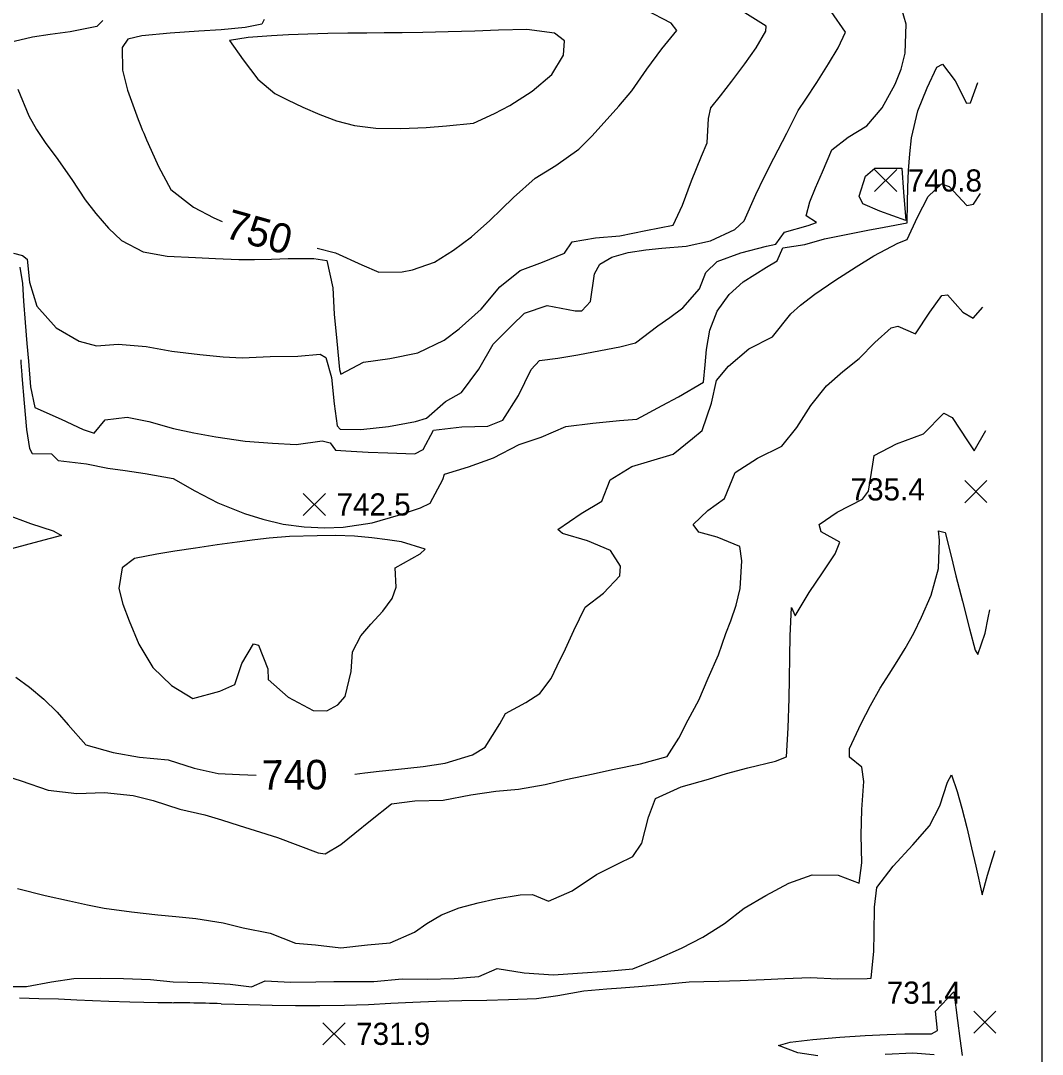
# Model space of a CAD drawing. Extents: x 2566079 to 2571326, y 424054 to 426896.
# Drawn here: x 2570611 to 2571303, y 425217 to 425917 of the extents above; entities that cross this region are included whole.
import ezdxf

# ---------------------------------------------------------------- set-up
doc = ezdxf.new("R2010")
doc.units = 0
for name, color, linetype in [('Contour_ADS_Label_Major', 7, 'Continuous'), ('Contour_ADS_Major', 7, 'Continuous'), ('Contour_ADS_Minor', 7, 'Continuous'), ('Contour_ADS_Spot_Elevation', 7, 'Continuous'), ('Contour_ADS_State_Plane_Border', 7, 'Continuous')]:
    doc.layers.add(name, color=color, linetype=linetype)

# ---------------------------------------------------------------- blocks, each defined once
blk = doc.blocks.new('S750')
at = {"layer": 'Contour_ADS_Spot_Elevation'}
for p, q in [((-0.5, 0.498), (0.5, -0.498)), ((-0.498, -0.5), (0.498, 0.5))]:
    blk.add_line(p, q, dxfattribs=at)

msp = doc.modelspace()

# ---------------------------------------------------------------- linework, layer by layer
at = {"layer": 'Contour_ADS_Major'}
for points in [[(2570811.84, 425762.74), (2570824.23, 425759.65), (2570842.23, 425751.41), (2570853.78, 425746.59), (2570869.41, 425746.79), (2570876.51, 425747.97), (2570891.26, 425753.24), (2570904.12, 425761.33), (2570916.5, 425770.5), (2570928.73, 425781.47), (2570936.67, 425789.06), (2570944.91, 425796.97), (2570959.43, 425810.1), (2570973.47, 425818.75), (2570989.15, 425829.87), (2570997.79, 425838.59), (2571006.2, 425847.78), (2571016.23, 425858.93), (2571025.08, 425869.19), (2571035.12, 425883.89), (2571045.19, 425897.82), (2571055.34, 425910.19), (2571051.6, 425915.17), (2571034.16, 425924.26)], [(2570776.12, 425917.51), (2570774.38, 425914.39), (2570763.17, 425912.13), (2570746.88, 425910.67), (2570731.75, 425909.75), (2570712.3, 425908.36), (2570693.3, 425906.6), (2570683.61, 425904.24), (2570679.87, 425898.73), (2570680.12, 425883.28), (2570683.52, 425869.84), (2570689.77, 425852.29)], [(2570697.41, 425833.73), (2570704.5, 425817.99), (2570712.8, 425802.58), (2570728.29, 425790.49), (2570741.94, 425783.26), (2570747.65, 425780.76)], [(2570837.35, 425406.4), (2570844.23, 425407.36), (2570854, 425408.53), (2570864.86, 425409.75), (2570883.65, 425411.67), (2570898.59, 425413.95), (2570917.07, 425419.53), (2570925.65, 425424.7), (2570935.55, 425440.67), (2570939.55, 425447.7), (2570953.14, 425455.05), (2570962.79, 425461.17), (2570970.26, 425471.28), (2570974.53, 425479.86), (2570980.03, 425491.47), (2570985.8, 425503.8), (2570993.46, 425519.6), (2571005.71, 425529.1), (2571016.8, 425540.86), (2571017.21, 425547.33), (2571010.58, 425557.96), (2570994.96, 425564.57), (2570977.94, 425569.52), (2570974.87, 425572.29), (2570990.63, 425583.09), (2571004.7, 425591.35), (2571010.34, 425605.88), (2571025.07, 425614.86), (2571035.51, 425618.11), (2571052.87, 425623.29), (2571066, 425633.77), (2571072.54, 425639.22), (2571078.86, 425657.88), (2571082.22, 425673.07), (2571090.38, 425682.94), (2571104.18, 425694.63), (2571120.16, 425702.63), (2571132.63, 425718.21), (2571139.15, 425724.15), (2571149, 425731.63), (2571162.46, 425740.74), (2571176.88, 425750.01), (2571188.88, 425757.54), (2571205.11, 425766.07), (2571211.41, 425768.57), (2571218.51, 425783.83), (2571225.64, 425797.83), (2571234.66, 425806.32), (2571239.91, 425804.58), (2571251.82, 425791.67), (2571256.29, 425792.61), (2571261.04, 425799.83)], [(2570600.98, 425582.5), (2570617.88, 425576.37), (2570633.21, 425571.34), (2570638.8, 425568.14), (2570623.46, 425563.99), (2570604.85, 425559.08)], [(2570607.87, 425472.23), (2570617.18, 425465.34), (2570626.89, 425457.24), (2570635.76, 425448.44), (2570643.23, 425440.03), (2570655.17, 425426.4), (2570673.69, 425421.07), (2570691.69, 425417.99), (2570711.08, 425416.3), (2570728.7, 425410.68), (2570744.85, 425407.01), (2570759.31, 425406.3), (2570770.68, 425405.87)], [(2571150.86, 425215.85), (2571137.48, 425217.8), (2571124.3, 425222.68), (2571132.12, 425224.95), (2571147.46, 425226.89), (2571165.72, 425228.44), (2571182.94, 425229.54), (2571197.84, 425230.24), (2571209.82, 425230.61), (2571227.98, 425230.56), (2571231.99, 425232.84), (2571231.99, 425232.84), (2571230.63, 425245.97), (2571242.93, 425259.06), (2571245.57, 425239.74), (2571247.16, 425227.51), (2571248.61, 425215.93)], [(2571229.74, 425216.37), (2571215.17, 425217.57), (2571196.61, 425216.58)]]:
    msp.add_lwpolyline(points, dxfattribs=at)
msp.add_arc((2571144.99, 426028.82), 488.25, 201.19619, 203.55166, dxfattribs=at)
at = {"layer": 'Contour_ADS_Minor'}
for points in [[(2570610.66, 425749.85), (2570612.3, 425738.73), (2570613.13, 425726.84), (2570614.25, 425712.41), (2570615.4, 425698.13), (2570616.35, 425686.14), (2570617.8, 425668.82), (2570620.73, 425654.88), (2570638.65, 425646.92), (2570653.47, 425639.87), (2570660.9, 425637.45), (2570668.35, 425646.59), (2570683.16, 425648.33), (2570697.9, 425645.31), (2570714.63, 425640.52), (2570728.49, 425637.58), (2570743.38, 425634.94), (2570763.08, 425632.07), (2570781.61, 425630.61), (2570797.72, 425629.7), (2570815.28, 425632.34), (2570820.75, 425630.95), (2570824.31, 425625.98), (2570834.95, 425625.22), (2570846.46, 425624.69), (2570859.69, 425624.05), (2570878.14, 425623.52), (2570883.6, 425626.32), (2570890.7, 425639.53), (2570909.78, 425641.69), (2570927.4, 425642.18), (2570937.72, 425646.29), (2570948.25, 425662.93), (2570956.86, 425680.48), (2570962.43, 425686.61), (2570974.84, 425688.19), (2570988.34, 425690.41), (2571003.84, 425693.34), (2571016.91, 425695.94), (2571027.51, 425698.53), (2571042.5, 425710.17), (2571050.8, 425715.87), (2571059.51, 425722.28), (2571070.9, 425735.29), (2571075.1, 425746.23), (2571082.71, 425753.73), (2571098.71, 425759.62), (2571116.08, 425764.02), (2571122.48, 425765.55), (2571128.45, 425773.59), (2571144.47, 425778.1), (2571150.1, 425780.15), (2571143.06, 425784.55), (2571145.5, 425794.18), (2571149.4, 425803.57), (2571154.01, 425814.51), (2571160.46, 425829.43), (2571171.4, 425837.86), (2571184.07, 425845.71), (2571194.51, 425857.83), (2571203.32, 425873.8), (2571207.37, 425883.98), (2571210.07, 425894.83), (2571210.63, 425914.52), (2571206.01, 425930.8)], [(2570606.35, 425759.46), (2570612.39, 425757.79), (2570615.55, 425755.35), (2570617.14, 425739.65), (2570622.13, 425723.42), (2570635.14, 425708.88), (2570650.76, 425699.65), (2570662.52, 425696.5), (2570677.26, 425697.74), (2570696.11, 425696.25), (2570713.49, 425692.9), (2570732.54, 425690.8), (2570748.3, 425689.14), (2570761.13, 425688.5), (2570780.13, 425689.38), (2570798.9, 425689.63), (2570813.93, 425691.03), (2570817.75, 425688.67), (2570821.7, 425675.23), (2570823.37, 425657.3), (2570825.37, 425642.44), (2570827.49, 425640.26), (2570841.48, 425639.97), (2570860.31, 425642.02), (2570878.53, 425645.42), (2570885.89, 425647.57), (2570898.72, 425658.93), (2570909.59, 425665.02), (2570921.31, 425680.79), (2570931.19, 425697.69), (2570943.62, 425710.42), (2570952.29, 425718.83), (2570967.65, 425723.93), (2570986.68, 425720.24), (2570991.06, 425720.27), (2570996.91, 425726.73), (2570999.61, 425745.4), (2571003.41, 425751.99), (2571011.52, 425756.73), (2571022.55, 425759.8), (2571034.41, 425761.68), (2571045.3, 425762.82), (2571061.74, 425764.05), (2571078.15, 425767.82), (2571094.77, 425775.28), (2571101.09, 425781.16), (2571108.92, 425799.15), (2571114.61, 425810.93), (2571121.02, 425823.62), (2571129.95, 425840.7), (2571137.54, 425855.9), (2571142.8, 425863.65), (2571150.22, 425874.93), (2571158.21, 425887.48), (2571164.78, 425898.32), (2571169.6, 425909.12), (2571159.94, 425923)], [(2570609.25, 425870.45), (2570616.68, 425852.44), (2570621.79, 425843.18), (2570628.3, 425833.58), (2570635.25, 425824.28), (2570645.81, 425809.35), (2570654.78, 425795.59), (2570662.04, 425786.13), (2570670.7, 425776.18), (2570679.47, 425767.89), (2570694.05, 425760.36), (2570710.37, 425757.36), (2570729.45, 425756.33), (2570743.11, 425755.8), (2570758.8, 425755.16), (2570769.41, 425755.18), (2570781.04, 425755.39), (2570792.29, 425755.64), (2570809.69, 425755.73), (2570818.52, 425754.38), (2570822.44, 425735.83), (2570823.49, 425717.99), (2570825.14, 425699.76), (2570826.99, 425680.49), (2570827.84, 425677.41), (2570843.31, 425685.58), (2570861.06, 425688.02), (2570880.13, 425691.75), (2570897.91, 425700.35), (2570908.17, 425708.21), (2570923.03, 425721.51), (2570935.69, 425736.56), (2570949.46, 425747.57), (2570964.52, 425753.29), (2570979.44, 425759.43), (2570984.48, 425767.09), (2571000.42, 425769.69), (2571016.75, 425771.17), (2571034.49, 425774.61), (2571053.02, 425778.27), (2571059.3, 425791.77), (2571065.33, 425808.42), (2571072.18, 425825.14), (2571076.06, 425834.03), (2571076.85, 425850.6), (2571078.55, 425857.86), (2571085.05, 425866.02), (2571092.59, 425875.75), (2571101.4, 425887.58), (2571109.07, 425898.34), (2571115.8, 425909.67), (2571116.02, 425913.13), (2571101.47, 425922.15)], [(2570666.74, 425916.92), (2570662.82, 425912.83), (2570644.78, 425909.34), (2570631.24, 425907.46), (2570619.15, 425905.66), (2570606.74, 425902.67)], [(2570611.98, 425676.35), (2570613.44, 425657.79), (2570615.05, 425639.83), (2570617.06, 425626.96), (2570618.86, 425623.75), (2570632.1, 425623.42), (2570636.45, 425618.85), (2570655.7, 425616.66), (2570670.13, 425613.84), (2570681.9, 425612.11), (2570695.47, 425610.17), (2570714.4, 425606.71), (2570729.01, 425598.5), (2570744.62, 425590.37), (2570762.75, 425583.12), (2570775.15, 425579.14), (2570788.88, 425575.89), (2570803.16, 425573.99), (2570817.05, 425573.36), (2570829.57, 425573.73), (2570849.21, 425576.71), (2570866.9, 425581.84), (2570881.9, 425586.92), (2570888.44, 425589.99), (2570897.1, 425606.01), (2570898.14, 425609.76), (2570914.45, 425614.63), (2570931.24, 425620.69), (2570948.74, 425629.69), (2570963.65, 425634.78), (2570980.38, 425642.05), (2570998.62, 425644.29), (2571016.57, 425645.98), (2571028.33, 425646.99), (2571045.46, 425656.09), (2571056.59, 425662.03), (2571073.43, 425671.97), (2571074.53, 425683.7), (2571075.47, 425694.22), (2571077.86, 425707.16), (2571082.79, 425720.18), (2571090.82, 425731.28), (2571100.38, 425739.98), (2571116.16, 425749.93), (2571123.45, 425754.09), (2571127.18, 425763.02), (2571142.06, 425765.12), (2571155.37, 425768.96), (2571173.51, 425772.68), (2571184.77, 425774.85), (2571195.77, 425776.97), (2571211.35, 425779.96), (2571211.66, 425793.64), (2571211.9, 425803.84), (2571212.35, 425815.25), (2571213.14, 425826.67), (2571214.38, 425837.5), (2571218.71, 425855.78), (2571224.88, 425871.28), (2571231.54, 425885.44), (2571235.34, 425887.34), (2571243.83, 425876.04), (2571251.64, 425860.94), (2571254.41, 425861.24), (2571259.37, 425875.05)], [(2570596.26, 425406.84), (2570611.38, 425401.99), (2570629.73, 425395.57), (2570649.21, 425393.48), (2570667.9, 425394.11), (2570687.43, 425392.17), (2570700.98, 425388.75), (2570719, 425382.84), (2570735.76, 425379.01), (2570747.16, 425375.66), (2570759.21, 425371.81), (2570770.04, 425368.31), (2570784.97, 425363.67), (2570798.78, 425358.38), (2570812.6, 425353.14), (2570817.23, 425352.59), (2570828.01, 425358.94), (2570837.5, 425366.49), (2570848.14, 425375.07), (2570862.36, 425386.36), (2570878.16, 425388.48), (2570897.18, 425388.86), (2570915.87, 425392.54), (2570932.82, 425394.94), (2570948.28, 425396.3), (2570966.2, 425399.59), (2570980.28, 425402.81), (2570998.74, 425406.81), (2571011.93, 425409.58), (2571030.89, 425413.59), (2571048.97, 425418.54), (2571056.72, 425430.98), (2571063.06, 425443.4), (2571070.27, 425456.69), (2571076.59, 425471.45), (2571083.75, 425487.35), (2571088.72, 425501.84), (2571091.92, 425510.43), (2571095.58, 425521.07), (2571098.43, 425532.18), (2571099.38, 425550.89), (2571098.17, 425560.69), (2571082.7, 425566.92), (2571070.3, 425570.34), (2571066.57, 425575.51), (2571076.43, 425584.97), (2571087.83, 425593.26), (2571094.99, 425610.85), (2571110.17, 425620.47), (2571126.48, 425628.61), (2571136.75, 425641.3), (2571146.21, 425656.17), (2571156.9, 425669.44), (2571167.92, 425679.3), (2571178.94, 425688.09), (2571189.47, 425698.86), (2571200.56, 425708.85), (2571205.06, 425709.96), (2571216.98, 425704.77), (2571226.67, 425719.46), (2571234.91, 425730.71), (2571238.74, 425731.1), (2571249.05, 425719.47), (2571256.19, 425715.38), (2571262.76, 425722.82)], [(2570810.75, 425290.95), (2570827.92, 425288.87), (2570845.91, 425290.84), (2570861.45, 425292.33), (2570877.79, 425299.48), (2570886.14, 425305.38), (2570896, 425311.21), (2570908.02, 425315.93), (2570920.9, 425319.47), (2570932.84, 425322.03), (2570949.48, 425324.8), (2570957.73, 425325.06), (2570968.47, 425320.57), (2570984.68, 425327.55), (2571001.09, 425338.6), (2571015.61, 425345.73), (2571025.68, 425350.84), (2571031.65, 425359.7), (2571036.33, 425377.43), (2571041.03, 425390.11), (2571058.35, 425397.82), (2571076.93, 425403.23), (2571089.05, 425406.87), (2571103.61, 425410.86), (2571122.27, 425415.24), (2571129.65, 425418.24), (2571130.73, 425437.84), (2571131.42, 425457.81), (2571131.75, 425470.98), (2571132.02, 425485.87), (2571132.25, 425500.26), (2571133.03, 425519.46), (2571135.69, 425513.64), (2571145.06, 425529.63), (2571154.04, 425542.87), (2571162.68, 425555.63), (2571165.84, 425563.73), (2571153.17, 425570.74), (2571151.78, 425575.61), (2571164.08, 425583.88), (2571181.19, 425592.81), (2571185.16, 425598.19), (2571188.15, 425616.51), (2571189.16, 425622.22), (2571204.19, 425630.34), (2571222.51, 425636.91), (2571236.13, 425650.9), (2571241.96, 425648.09), (2571252.34, 425632.23), (2571256.83, 425625.53), (2571264.62, 425639.34)], [(2570904.58, 425268.22), (2570921.48, 425269.53), (2570933.7, 425274.82), (2570952.12, 425271.87), (2570971.98, 425270.63), (2570988.26, 425271.63), (2571008.19, 425273.14), (2571025.61, 425274.69), (2571041.31, 425280.89), (2571058.54, 425288.58), (2571073.17, 425296.04), (2571087.72, 425305.39), (2571101.08, 425315.86), (2571115.63, 425324.34), (2571131.39, 425332.79), (2571147.16, 425338.31), (2571164.65, 425338.2), (2571178.91, 425332.62), (2571180.64, 425346.53), (2571180.36, 425365.27), (2571180.62, 425382.53), (2571181.97, 425401.45), (2571180.68, 425411.25), (2571172.38, 425417.99), (2571172.26, 425423.97), (2571180.34, 425440.93), (2571186.66, 425453.06), (2571193.2, 425464.73), (2571199.14, 425474.3), (2571204.66, 425482.73), (2571210.17, 425491.65), (2571215.88, 425502.09), (2571221.2, 425512.75), (2571227.75, 425527.74), (2571232.72, 425545.81), (2571233.34, 425564.88), (2571232.59, 425571.27), (2571237.06, 425570.2), (2571241.26, 425554.2), (2571244.31, 425540.8), (2571248.77, 425523.62), (2571253.69, 425504.91), (2571257.55, 425490.38), (2571259.17, 425487.48), (2571264.16, 425502.11), (2571266.25, 425512.46), (2571267.32, 425517.88)], [(2570746.91, 425251.05), (2570765.27, 425250.52), (2570781.55, 425250.04), (2570797.33, 425249.76), (2570813.77, 425249.76), (2570830.49, 425250.05), (2570846.65, 425250.59), (2570861.79, 425251.32), (2570876.7, 425252.1), (2570892.5, 425252.78), (2570909.76, 425253.23), (2570926.84, 425253.53), (2570941.57, 425253.79), (2570960.48, 425254.65), (2570974.81, 425256.66), (2570992.45, 425259.81), (2571008.16, 425261.07), (2571017.85, 425261.74), (2571029.48, 425262.59), (2571047.56, 425264.18), (2571063.79, 425265.79), (2571073.8, 425265.98), (2571083.79, 425266.28), (2571098.32, 425266.83), (2571114.5, 425267.51), (2571128.5, 425268.14), (2571145.82, 425268.72), (2571164.39, 425267.94), (2571184.27, 425268.16), (2571186.94, 425268.41), (2571188.9, 425286.66), (2571188.99, 425298.85), (2571189.26, 425316.34), (2571190.94, 425329.74), (2571201.95, 425344.25), (2571215.27, 425358.73), (2571226.5, 425371.45), (2571233.51, 425385.1), (2571238.78, 425401), (2571241.45, 425406.08), (2571245.37, 425394.72), (2571248.4, 425383.52), (2571251.74, 425370.36), (2571255.02, 425356.67), (2571257.92, 425344.16), (2571262.09, 425324.73), (2571265.89, 425338.21), (2571269.24, 425349.1), (2571270.96, 425354.72)], [(2570609.1, 425329.15), (2570627.8, 425324.26), (2570644.19, 425320.68), (2570656.32, 425317.99), (2570667.64, 425315.66), (2570686.21, 425313.26), (2570704.01, 425311.28), (2570716.24, 425310.07), (2570729.78, 425308.67), (2570748.25, 425305.89), (2570761.86, 425302.49), (2570780.2, 425298.79), (2570797.27, 425292.05), (2570810.75, 425290.95)], [(2570598.99, 425262.61), (2570615.06, 425262.62), (2570631.95, 425265.78), (2570647.25, 425268.02), (2570665.26, 425268.26), (2570680.68, 425268.08), (2570699.08, 425267.52), (2570714.5, 425265.94), (2570734.3, 425265.47), (2570752.94, 425264.32), (2570767.4, 425262.47), (2570776.65, 425266.44), (2570793.92, 425265.57), (2570810.91, 425265.93), (2570823.18, 425266.05), (2570834.79, 425266.11), (2570850.29, 425266.13), (2570869.45, 425268), (2570886.37, 425267.6), (2570904.58, 425268.22)], [(2570610.4, 425255.01), (2570623.39, 425254.68), (2570636.75, 425254.24), (2570649.1, 425253.76), (2570659.77, 425253.28), (2570670.81, 425252.83), (2570684.96, 425252.39), (2570703.98, 425251.97)]]:
    msp.add_lwpolyline(points, dxfattribs=at)
for points in [[(2570883.54, 425908.86), (2570869.39, 425908.64), (2570857.32, 425908.53), (2570845.56, 425908.45), (2570832.78, 425908.29), (2570819.25, 425908.03), (2570805.6, 425907.65), (2570792.55, 425907.16), (2570780.92, 425906.58), (2570765.16, 425905.34), (2570752.56, 425903.29), (2570761.9, 425890.29), (2570771.67, 425877.25), (2570783.36, 425867.58), (2570791.8, 425863.16), (2570802.3, 425858.18), (2570813.64, 425853.26), (2570825, 425848.97), (2570837.23, 425845.73), (2570851.6, 425843.92), (2570868.62, 425843.72), (2570885.72, 425844.56), (2570899.6, 425845.66), (2570917.71, 425847.47), (2570932.08, 425854.01), (2570942.39, 425859.46), (2570957.59, 425869.03), (2570970.73, 425880.42), (2570978.72, 425893.37), (2570979.39, 425903.13), (2570972.69, 425908.33), (2570953.95, 425910.81), (2570934.66, 425910.28), (2570918.73, 425909.79), (2570900.7, 425909.28), (2570883.54, 425908.86)], [(2571207.81, 425816.92), (2571209.02, 425800.69), (2571210.53, 425781.43), (2571192.82, 425787.8), (2571181.38, 425792.66), (2571178.86, 425797.94), (2571183.22, 425811.45), (2571189.49, 425816.84), (2571207.81, 425816.92)], [(2570727.75, 425457.7), (2570746.11, 425462.78), (2570756.11, 425467.13), (2570760.87, 425481.4), (2570768.7, 425494.79), (2570772.25, 425493.89), (2570778.48, 425477.76), (2570778.78, 425470.56), (2570792.32, 425458.74), (2570809.16, 425449.58), (2570818.37, 425449.32), (2570825.95, 425453.54), (2570830.92, 425459.05), (2570834.85, 425476.03), (2570835.76, 425489.28), (2570841.39, 425500.16), (2570848.34, 425508.07), (2570856.27, 425516.87), (2570862.59, 425525.53), (2570865.44, 425533.13), (2570864.75, 425546.21), (2570881.6, 425555.77), (2570884.94, 425558.8), (2570869.11, 425563.76), (2570859.54, 425565.24), (2570848.91, 425566.65), (2570837.13, 425567.67), (2570824.34, 425568.04), (2570811.83, 425567.95), (2570793.25, 425567.45), (2570779.37, 425566.44), (2570769.7, 425565.3), (2570757.79, 425563.72), (2570744.18, 425561.79), (2570729.62, 425559.63), (2570715.5, 425557.49), (2570703.39, 425555.61), (2570688.12, 425552.5), (2570679.82, 425546.3), (2570677.73, 425532.34), (2570680.42, 425521.64), (2570684.53, 425510.31), (2570691.12, 425494.59), (2570700.67, 425478.82), (2570713.38, 425466.59), (2570727.75, 425457.7)]]:
    msp.add_lwpolyline(points, close=True, dxfattribs=at)
for centre, radius, start, end in [((2580583.79, 426440.99), 10001.09, 184.323014, 184.384894), ((2570901.72, 434744.87), 9494.96, 268.806697, 268.872244), ((2570551.55, 416931.09), 8322.26, 88.801044, 88.875758), ((2570606.43, 419509.95), 5742.82, 88.5983, 88.810064)]:
    msp.add_arc(centre, radius, start, end, dxfattribs=at)
at = {"layer": 'Contour_ADS_State_Plane_Border'}
msp.add_lwpolyline([(2566079.33, 424077.11), (2571302.93, 424077.11), (2571302.93, 426873.74), (2566079.33, 426873.74), (2566079.33, 424077.11)], close=True, dxfattribs=at)

# ---------------------------------------------------------------- block references
at = {"layer": 'Contour_ADS_Spot_Elevation', "xscale": 15, "yscale": 15}
for p in [(2571196.85, 425808.58), (2571257.92, 425597.86), (2570810.02, 425589.17), (2571263.98, 425238.57), (2570823.3, 425230.64)]:
    msp.add_blockref('S750', p, dxfattribs=at)

# ---------------------------------------------------------------- texts
at = {"layer": 'Contour_ADS_Label_Major'}
for s, rotation, p in [('750', 344.31715, (2570748.43, 425770.15)), ('740', 0.45461, (2570774.37, 425395.91))]:
    msp.add_text(s, height=20, rotation=rotation, dxfattribs=at).set_placement(p)
at = {"layer": 'Contour_ADS_Spot_Elevation'}
for s, p in [('740.8', (2571211.85, 425801.08)), ('735.4', (2571173.12, 425591.89)), ('742.5', (2570825.02, 425581.67)), ('731.4', (2571197.61, 425251.03)), ('731.9', (2570838.3, 425223.14))]:
    msp.add_text(s, height=15, dxfattribs=at).set_placement(p)

doc.saveas('drawing.dxf')
